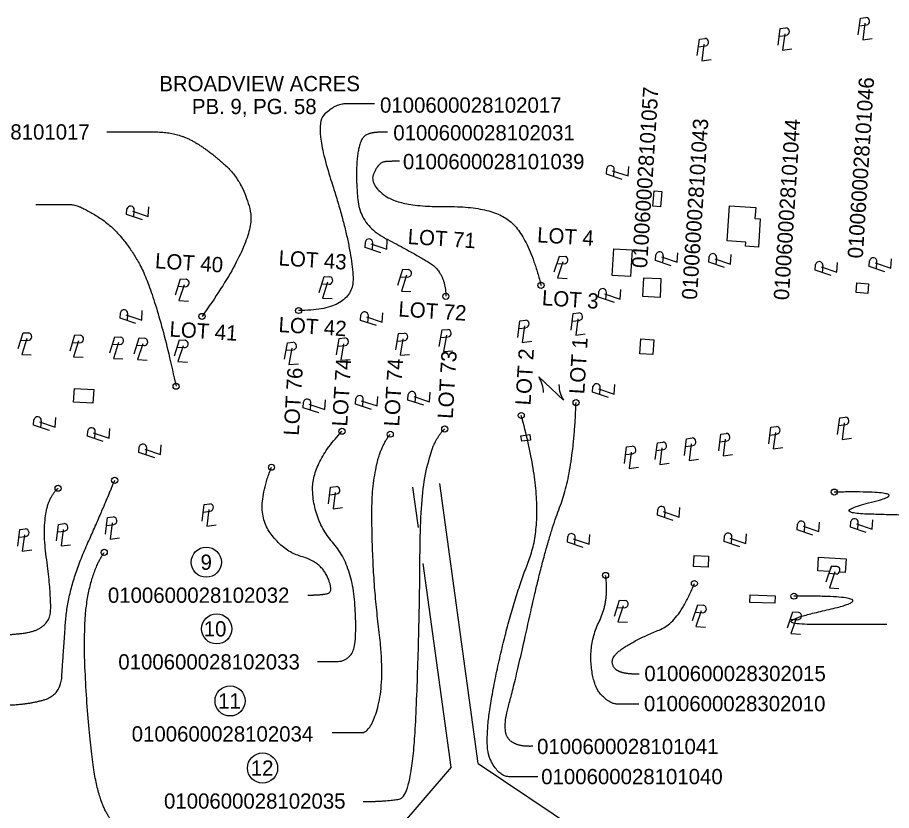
# Model space of a CAD drawing. Extents: x 1571291 to 1576333, y 700252 to 704384.
# Drawn here: x 1572970 to 1574575, y 702532 to 703989 of the extents above; entities that cross this region are included whole.
import ezdxf

# ---------------------------------------------------------------- set-up
doc = ezdxf.new("R2010")
doc.units = 0
doc.layers.add('RW_X_CL_100_Bearings', color=7, linetype='Continuous')
doc.layers.add('RW_X_CL_100_Cardinal_Points', color=7, linetype='Continuous')

msp = doc.modelspace()

# ---------------------------------------------------------------- linework, layer by layer
at = {"layer": 'RW_X_CL_100_Bearings'}
for p, q in [((1573706.1, 703051.9), (1573696, 703126.4)), ((1573815.6, 702618.7), (1573745.5, 703133.2)), ((1573766.1, 702611.9), (1573715.1, 702986.1)), ((1573766.1, 702611.9), (1573530.6, 702338.1)), ((1573815.6, 702618.7), (1574165.4, 702384.7))]:
    msp.add_line(p, q, dxfattribs=at)
for points in [[(1574136.6, 703642.4), (1574139.1, 703670.4), (1574153.3, 703669.2), (1574150.8, 703641.1)], [(1574273, 703578.4), (1574277, 703642.9), (1574325.3, 703640), (1574324, 703619.7), (1574333.5, 703619.1), (1574330.3, 703567.1), (1574306.6, 703568.5), (1574307.1, 703576.3)], [(1574061.8, 703515.2), (1574064.7, 703563.8), (1574098.4, 703561.8), (1574095.4, 703513.2)], [(1574118.4, 703476.4), (1574120.2, 703510.8), (1574151.5, 703509.2), (1574149.7, 703474.7)], [(1574509.7, 703483.4), (1574511, 703501.2), (1574532.3, 703499.6), (1574531.1, 703481.9)], [(1574114.4, 703398.5), (1574138.6, 703396.7), (1574136.6, 703369.6), (1574112.4, 703371.3)], [(1573073.3, 703282.5), (1573075, 703307.6), (1573110.5, 703305.3), (1573108.8, 703280.2)], [(1573896, 703210.4), (1573894.3, 703220.7), (1573910.5, 703222.9), (1573912, 703212.6)], [(1574237.8, 702979.2), (1574210.9, 702980.8), (1574212.1, 703000.9), (1574239, 702999.3)], [(1574314.6, 702914.6), (1574315.1, 702928.5), (1574361.1, 702926.9), (1574360.7, 702913.1)]]:
    msp.add_lwpolyline(points, close=True, dxfattribs=at)
msp.add_lwpolyline([(1574474.8, 702980.6), (1574464.5, 702981.4), (1574461.1, 702971.5), (1574439.5, 702972.7), (1574440.9, 702997.4), (1574491.2, 702994.5), (1574489.8, 702969.8), (1574479.2, 702970.4)], dxfattribs=at)
for centre, radius in [((1573931.3, 703496.8), 5.6), ((1573756.5, 703476.7), 5.6), ((1573309, 703439.7), 5.6), ((1573486.2, 703450.6), 5.6), ((1573261.4, 703311.6), 5.6), ((1573995.6, 703281.6), 5.6), ((1573895, 703257.8), 5.6), ((1573754.5, 703233.1), 5.6), ((1573565.9, 703228.9), 5.6), ((1573654.4, 703223.5), 5.6), ((1573436.5, 703162.8), 5.6), ((1573148.7, 703138.8), 5.6), ((1573044.7, 703124.2), 5.6), ((1574469.6, 703117.1), 5.6), ((1573129.5, 703006.5), 5.6), ((1573316.8, 702988.4), 27.7), ((1574049.8, 702964.1), 5.6), ((1574212.8, 702949.3), 5.6), ((1574395.6, 702926), 5.6), ((1573335.9, 702866), 27.7), ((1573360.5, 702733.7), 27.7), ((1573420.1, 702610.4), 27.7)]:
    msp.add_circle(centre, radius, dxfattribs=at)
msp.add_arc((1574473.2, 702973.9), 6.9, 329.6631, 77.0927, dxfattribs=at)
for points in [[(1573625.7, 703830), (1573587.7, 703830), (1573554, 703830), (1573512.8, 703790.9), (1573580.9, 703581.9), (1573591.4, 703450), (1573486.2, 703450.6)], [(1573134.2, 703778.5), (1573185.1, 703778.5), (1573262.4, 703778.5), (1573322.8, 703744.6), (1573386.1, 703684.9), (1573409.1, 703580.1), (1573309, 703439.7)], [(1573649.2, 703777.9), (1573618.5, 703779.3), (1573597.8, 703764.1), (1573590.4, 703699.6), (1573599.9, 703606.8), (1573693.8, 703558.2), (1573756.4, 703520.3), (1573756.5, 703476.7)], [(1573671.7, 703724.9), (1573654.9, 703724.7), (1573634.2, 703723.1), (1573615, 703683.6), (1573673.5, 703640.5), (1573842.1, 703642.4), (1573908.9, 703584.8), (1573931.3, 703496.8)], [(1573003.6, 703645.3), (1573051.8, 703645.3), (1573083.5, 703645.3), (1573161.2, 703594.5), (1573224.1, 703482.9), (1573261.4, 703311.6)], [(1573916.5, 702650.4), (1573882, 702648.8), (1573859.6, 702681.9), (1573884.1, 702768.8), (1573940.6, 703025.1), (1573991.2, 703154.9), (1573995.6, 703281.6)], [(1573925.7, 702594.5), (1573891.2, 702594.5), (1573853.9, 702594.5), (1573822.9, 702656.4), (1573873.5, 702900.6), (1573944.3, 703082.6), (1573895, 703257.8)], [(1573521, 702806.3), (1573545.2, 702806.3), (1573573.2, 702806.3), (1573594.6, 702835.5), (1573584.9, 702983.2), (1573516.2, 703061.6), (1573508.2, 703168.1), (1573565.9, 703228.9)], [(1573548, 702675.7), (1573583.1, 702675.7), (1573619.6, 702675), (1573645.1, 702775.1), (1573621.8, 702958.7), (1573619.7, 703180.2), (1573654.4, 703223.5)], [(1573604.8, 702548.9), (1573648.6, 702548.9), (1573695.1, 702558.6), (1573708.1, 702849.3), (1573710.7, 703193.5), (1573754.5, 703233.1)], [(1573503.1, 702928), (1573528.3, 702928), (1573551.4, 702934.2), (1573526.6, 702989.2), (1573455.3, 703008.9), (1573405.8, 703086.9), (1573436.5, 703162.8)], [(1572939, 702725.9), (1572983.1, 702725.9), (1573049.4, 702743.7), (1573053.8, 702812.4), (1573062.7, 702941.2), (1573128.7, 703089.5), (1573148.7, 703138.8)], [(1572919.6, 702854.8), (1572979.9, 702854.8), (1573023.3, 702870.6), (1573035.2, 702906.9), (1573010.7, 703093.5), (1573044.7, 703124.2)], [(1574633.4, 703074.3), (1574608.3, 703074.3), (1574457.1, 703078.9), (1574624.6, 703119.9), (1574469.6, 703117.1)], [(1573224.8, 702489.4), (1573170, 702487.3), (1573128.6, 702526.8), (1573105.3, 702620.5), (1573088.8, 702862.5), (1573107.7, 702975.4), (1573129.5, 703006.5)], [(1574110.6, 702727.8), (1574085.9, 702727.8), (1574058.5, 702727.8), (1574026.6, 702760.2), (1574019.9, 702842.4), (1574056.7, 702917.9), (1574049.8, 702964.1)], [(1574111.5, 702782.7), (1574084.5, 702782.7), (1574062.1, 702793.9), (1574062.1, 702818.6), (1574115.1, 702851), (1574184.7, 702878.4), (1574212.8, 702949.3)], [(1574566, 702874), (1574534.6, 702874), (1574336.2, 702874), (1574575.6, 702927.4), (1574395.6, 702926)]]:
    msp.add_open_spline(points, degree=2, dxfattribs=at)
at = {"layer": 'RW_X_CL_100_Cardinal_Points'}
for p, q in [((1574515.6, 703973.4), (1574528.5, 703975)), ((1574524.4, 703968.2), (1574524.4, 703968.2)), ((1574368.5, 703954.3), (1574381.3, 703955.9)), ((1574377.2, 703949.1), (1574377.2, 703949.1)), ((1574220.2, 703935), (1574233.1, 703936.7)), ((1574229, 703929.9), (1574229, 703929.9)), ((1574064.7, 703696.6), (1574065.6, 703709.5)), ((1574071.5, 703704.2), (1574071.5, 703704.2)), ((1573183.9, 703622.3), (1573184.7, 703635.2)), ((1573190.6, 703629.9), (1573190.6, 703629.9)), ((1573621.7, 703561.9), (1573622.4, 703574.8)), ((1573628.4, 703569.5), (1573628.4, 703569.5)), ((1574154.9, 703538.2), (1574155.8, 703551.1)), ((1574161.6, 703545.7), (1574161.6, 703545.7)), ((1574252.8, 703534.9), (1574253.7, 703547.8)), ((1574259.5, 703542.4), (1574259.5, 703542.4)), ((1574547, 703527.2), (1574547.9, 703540.1)), ((1573960.5, 703537.1), (1573973.5, 703536.3)), ((1573968.1, 703530.4), (1573968.1, 703530.4)), ((1574448, 703520.1), (1574448.9, 703533)), ((1574454.8, 703527.7), (1574454.8, 703527.7)), ((1574553.8, 703534.7), (1574553.8, 703534.7)), ((1573673.4, 703512.7), (1573686.3, 703512.1)), ((1573265.2, 703495.1), (1573278.2, 703494.4)), ((1573528.8, 703499.5), (1573541.7, 703498.9)), ((1573536.5, 703492.9), (1573536.5, 703492.9)), ((1573681.1, 703506.1), (1573681.1, 703506.1)), ((1573272.9, 703488.4), (1573272.9, 703488.4)), ((1574050.4, 703470.6), (1574051.2, 703483.5)), ((1574057.1, 703478.2), (1574057.1, 703478.2)), ((1573172, 703431.8), (1573172.8, 703444.8)), ((1573178.7, 703439.4), (1573178.7, 703439.4)), ((1573613.5, 703427.9), (1573614.3, 703440.9)), ((1573620.2, 703435.6), (1573620.2, 703435.6)), ((1573988.7, 703430.8), (1574001.6, 703432.5)), ((1573890.6, 703417.4), (1573903.4, 703419.1)), ((1573899.4, 703412.3), (1573899.4, 703412.3)), ((1573997.5, 703425.7), (1573997.5, 703425.7)), ((1572976.3, 703396.4), (1572989.2, 703395.8)), ((1573667.4, 703394.4), (1573680.4, 703395.5)), ((1573747.3, 703401), (1573760.2, 703402.1)), ((1573755.8, 703395.5), (1573755.8, 703395.5)), ((1572984, 703389.8), (1572984, 703389.8)), ((1573071.6, 703392.1), (1573084.6, 703391.5)), ((1573079.3, 703385.5), (1573079.3, 703385.5)), ((1573144.8, 703388.8), (1573157.7, 703388.3)), ((1573152.5, 703382.3), (1573152.5, 703382.3)), ((1573189.3, 703386.8), (1573202.2, 703386.1)), ((1573197, 703380.1), (1573197, 703380.1)), ((1573263.4, 703383), (1573276.3, 703382.4)), ((1573558.6, 703385.4), (1573571.5, 703386.4)), ((1573567.1, 703379.8), (1573567.1, 703379.8)), ((1573675.9, 703388.9), (1573675.9, 703388.9)), ((1573271.1, 703376.4), (1573271.1, 703376.4)), ((1573463.4, 703377.5), (1573476.4, 703378.5)), ((1573471.9, 703371.9), (1573471.9, 703371.9)), ((1573972.7, 703285.8), (1573927.3, 703328.6)), ((1573950, 703307.2), (1573950, 703307.2)), ((1574039.2, 703296), (1574040.1, 703308.9)), ((1574046, 703303.6), (1574046, 703303.6)), ((1573604.2, 703274.2), (1573604.9, 703287.1)), ((1573700.4, 703281.8), (1573701.2, 703294.7)), ((1573707.1, 703289.4), (1573707.1, 703289.4)), ((1573508, 703267.7), (1573508.8, 703280.6)), ((1573514.7, 703275.3), (1573514.7, 703275.3)), ((1573610.9, 703281.8), (1573610.9, 703281.8)), ((1573013.2, 703235.4), (1573014, 703248.3)), ((1573019.9, 703243), (1573019.9, 703243)), ((1574477.9, 703239.3), (1574490.7, 703241)), ((1573112.1, 703215.1), (1573112.9, 703228.1)), ((1573118.8, 703222.7), (1573118.8, 703222.7)), ((1574351.4, 703222), (1574364.2, 703223.8)), ((1574486.6, 703234.2), (1574486.6, 703234.2)), ((1574259.4, 703209.5), (1574272.2, 703211.3)), ((1574268.2, 703204.4), (1574268.2, 703204.4)), ((1574360.1, 703216.9), (1574360.1, 703216.9)), ((1573206.6, 703185.3), (1573207.4, 703198.2)), ((1573213.3, 703192.9), (1573213.3, 703192.9)), ((1574086.6, 703186), (1574099.4, 703187.7)), ((1574143.1, 703193.7), (1574156, 703195.4)), ((1574151.9, 703188.6), (1574151.9, 703188.6)), ((1574196.8, 703201), (1574209.7, 703202.7)), ((1574205.6, 703195.9), (1574205.6, 703195.9)), ((1574095.4, 703180.9), (1574095.4, 703180.9)), ((1573543.3, 703111.9), (1573556.1, 703113.7)), ((1573552.1, 703106.8), (1573552.1, 703106.8)), ((1573311.3, 703080.3), (1573324.1, 703082)), ((1573320, 703075.2), (1573320, 703075.2)), ((1574158.3, 703070.5), (1574159.2, 703083.4)), ((1574165, 703078), (1574165, 703078)), ((1574512.6, 703048.1), (1574513.6, 703061)), ((1573044, 703043.9), (1573056.8, 703045.6)), ((1573134, 703056.1), (1573146.9, 703057.9)), ((1573142.8, 703051), (1573142.8, 703051)), ((1574414.8, 703043.5), (1574415.7, 703056.4)), ((1574421.6, 703051.1), (1574421.6, 703051.1)), ((1574519.4, 703055.6), (1574519.4, 703055.6)), ((1572972.7, 703034.1), (1572985.5, 703035.9)), ((1572981.5, 703029), (1572981.5, 703029)), ((1573052.7, 703038.8), (1573052.7, 703038.8)), ((1573993.1, 703020.7), (1573993.9, 703033.6)), ((1573999.8, 703028.3), (1573999.8, 703028.3)), ((1574280.8, 703021.8), (1574281.7, 703034.7)), ((1574287.5, 703029.3), (1574287.5, 703029.3)), ((1574459.9, 702968), (1574472.8, 702967)), ((1574467.4, 702961.1), (1574467.4, 702961.1)), ((1574071.1, 702905.3), (1574084, 702904.6)), ((1574078.8, 702898.7), (1574078.8, 702898.7)), ((1574214.6, 702896.6), (1574227.6, 702895.7)), ((1574222.2, 702889.8), (1574222.2, 702889.8)), ((1574389.2, 702883.7), (1574402.1, 702882.7)), ((1574396.7, 702876.9), (1574396.7, 702876.9))]:
    msp.add_line(p, q, dxfattribs=at)
for points in [[(1574513.5, 703957), (1574517.5, 703987.4), (1574527.7, 703988.8)], [(1574525.8, 703978.1), (1574521.8, 703947.7), (1574539.1, 703950)], [(1574366.3, 703937.9), (1574370.3, 703968.3), (1574380.5, 703969.7)], [(1574378.6, 703959), (1574374.6, 703928.6), (1574391.9, 703930.9)], [(1574218.1, 703918.7), (1574222, 703949.1), (1574232.3, 703950.4)], [(1574230.4, 703939.7), (1574226.3, 703909.4), (1574243.7, 703911.6)], [(1574080.4, 703691.4), (1574051.3, 703701), (1574051.9, 703711.4)], [(1574062.1, 703707.4), (1574091.1, 703697.7), (1574092.2, 703715.1)], [(1573199.5, 703617.1), (1573170.4, 703626.8), (1573171, 703637.1)], [(1573181.2, 703633.2), (1573210.2, 703623.4), (1573211.3, 703640.9)], [(1573637.3, 703556.7), (1573608.2, 703566.3), (1573608.8, 703576.6)], [(1573618.9, 703572.8), (1573648, 703563.1), (1573649, 703580.5)], [(1574152.2, 703549.1), (1574181.2, 703539.1), (1574182.4, 703556.5)], [(1573955.3, 703521.5), (1573965, 703550.6), (1573975.3, 703549.9)], [(1573971.4, 703539.8), (1573961.6, 703510.8), (1573979, 703509.7)], [(1574170.4, 703532.9), (1574141.4, 703542.7), (1574142.1, 703553)], [(1574268.3, 703529.6), (1574239.3, 703539.4), (1574240.1, 703549.7)], [(1574250.2, 703545.8), (1574279.1, 703535.8), (1574280.3, 703553.2)], [(1574562.6, 703521.9), (1574533.6, 703531.7), (1574534.3, 703542)], [(1574544.4, 703538.1), (1574573.3, 703528.1), (1574574.6, 703545.5)], [(1573668.4, 703497), (1573677.6, 703526.3), (1573687.9, 703525.8)], [(1574463.6, 703514.8), (1574434.6, 703524.7), (1574435.3, 703535)], [(1574445.4, 703531), (1574474.3, 703521), (1574475.6, 703538.5)], [(1573260.2, 703479.4), (1573269.5, 703508.6), (1573279.8, 703508.1)], [(1573523.8, 703483.8), (1573533, 703513), (1573543.3, 703512.5)], [(1573684.2, 703515.6), (1573674.9, 703486.4), (1573692.4, 703485.6)], [(1573276, 703497.9), (1573266.6, 703468.8), (1573284.1, 703467.9)], [(1573539.6, 703502.4), (1573530.3, 703473.2), (1573547.7, 703472.4)], [(1574066, 703465.4), (1574036.9, 703475.1), (1574037.5, 703485.4)], [(1574047.7, 703481.5), (1574076.7, 703471.7), (1574077.8, 703489.1)], [(1573187.6, 703426.6), (1573158.5, 703436.3), (1573159.1, 703446.6)], [(1573169.3, 703442.7), (1573198.3, 703433), (1573199.4, 703450.4)], [(1573610.8, 703438.8), (1573639.8, 703429.1), (1573640.9, 703446.5)], [(1573986.7, 703414.4), (1573990.4, 703444.9), (1574000.7, 703446.2)], [(1573629.1, 703422.8), (1573600, 703432.4), (1573600.7, 703442.7)], [(1573888.6, 703401), (1573892.3, 703431.5), (1573902.5, 703432.9)], [(1573998.8, 703435.5), (1573995, 703405.2), (1574012.3, 703407.5)], [(1573744.4, 703384.8), (1573749.8, 703415), (1573760.1, 703415.9)], [(1573900.7, 703422.2), (1573896.9, 703391.8), (1573914.2, 703394.2)], [(1572971.4, 703380.7), (1572980.5, 703409.9), (1572990.8, 703409.5)], [(1572987.1, 703399.3), (1572977.9, 703370.1), (1572995.3, 703369.3)], [(1573066.7, 703376.4), (1573075.8, 703405.7), (1573086.2, 703405.2)], [(1573139.8, 703373.1), (1573149, 703402.4), (1573159.3, 703401.9)], [(1573184.3, 703371.1), (1573193.6, 703400.3), (1573203.9, 703399.8)], [(1573258.4, 703367.3), (1573267.7, 703396.6), (1573278, 703396)], [(1573555.7, 703369.2), (1573561, 703399.4), (1573571.3, 703400.2)], [(1573664.6, 703378.2), (1573669.9, 703408.4), (1573680.2, 703409.2)], [(1573677.8, 703398.7), (1573672.4, 703368.5), (1573689.8, 703370)], [(1573757.7, 703405.3), (1573752.2, 703375.2), (1573769.6, 703376.6)], [(1573082.4, 703395), (1573073.2, 703365.8), (1573090.7, 703365)], [(1573155.6, 703391.7), (1573146.3, 703362.5), (1573163.8, 703361.8)], [(1573200.1, 703389.6), (1573190.7, 703360.5), (1573208.2, 703359.6)], [(1573274.2, 703385.9), (1573264.8, 703356.7), (1573282.3, 703355.8)], [(1573460.6, 703361.3), (1573465.9, 703391.5), (1573476.2, 703392.3)], [(1573473.8, 703381.7), (1573468.4, 703351.6), (1573485.8, 703353)], [(1573568.9, 703389.6), (1573563.5, 703359.5), (1573580.9, 703360.9)], [(1573697.7, 703292.7), (1573726.7, 703283), (1573727.8, 703300.4)], [(1574054.9, 703290.8), (1574025.8, 703300.5), (1574026.4, 703310.8)], [(1574036.6, 703306.9), (1574065.6, 703297.1), (1574066.7, 703314.5)], [(1573505.3, 703278.6), (1573534.3, 703268.9), (1573535.4, 703286.3)], [(1573619.8, 703269), (1573590.7, 703278.6), (1573591.3, 703288.9)], [(1573601.4, 703285), (1573630.5, 703275.3), (1573631.5, 703292.8)], [(1573716, 703276.6), (1573686.9, 703286.2), (1573687.5, 703296.5)], [(1573523.6, 703262.5), (1573494.5, 703272.1), (1573495.2, 703282.5)], [(1573010.5, 703246.3), (1573039.5, 703236.5), (1573040.6, 703254)], [(1574475.8, 703222.9), (1574479.6, 703253.4), (1574489.8, 703254.8)], [(1573028.8, 703230.2), (1572999.7, 703239.8), (1573000.3, 703250.2)], [(1574349.3, 703205.7), (1574353.1, 703236.1), (1574363.3, 703237.5)], [(1574488, 703244.1), (1574484.1, 703213.7), (1574501.4, 703216.1)], [(1573127.8, 703209.9), (1573098.6, 703219.6), (1573099.3, 703229.9)], [(1573109.4, 703226), (1573138.4, 703216.3), (1573139.5, 703233.7)], [(1574257.4, 703193.2), (1574261.1, 703223.6), (1574271.3, 703225)], [(1574361.5, 703226.8), (1574357.6, 703196.5), (1574374.9, 703198.8)], [(1573203.9, 703196.2), (1573232.9, 703186.5), (1573234, 703203.9)], [(1574141.1, 703177.3), (1574144.9, 703207.8), (1574155.1, 703209.1)], [(1574194.8, 703184.6), (1574198.6, 703215.1), (1574208.8, 703216.5)], [(1574207, 703205.8), (1574203.1, 703175.4), (1574220.4, 703177.8)], [(1574269.5, 703214.3), (1574265.7, 703183.9), (1574283, 703186.3)], [(1573222.2, 703180.1), (1573193.1, 703189.8), (1573193.8, 703200.1)], [(1574084.6, 703169.6), (1574088.3, 703200.1), (1574098.6, 703201.4)], [(1574096.7, 703190.7), (1574092.9, 703160.4), (1574110.2, 703162.7)], [(1574153.3, 703198.4), (1574149.4, 703168.1), (1574166.7, 703170.4)], [(1573541.3, 703095.6), (1573545, 703126), (1573555.3, 703127.4)], [(1573553.4, 703116.7), (1573549.6, 703086.3), (1573566.9, 703088.7)], [(1573309.3, 703063.9), (1573313, 703094.4), (1573323.2, 703095.8)], [(1573321.4, 703085.1), (1573317.5, 703054.7), (1573334.9, 703057.1)], [(1574173.9, 703065.2), (1574144.8, 703075), (1574145.5, 703085.3)], [(1574155.6, 703081.3), (1574184.6, 703071.4), (1574185.8, 703088.9)], [(1573041.9, 703027.5), (1573045.7, 703057.9), (1573055.9, 703059.3)], [(1573132, 703039.8), (1573135.7, 703070.2), (1573146, 703071.6)], [(1573144.1, 703060.9), (1573140.3, 703030.5), (1573157.6, 703032.9)], [(1574412.2, 703054.4), (1574441.2, 703044.5), (1574442.4, 703061.9)], [(1574528.2, 703042.7), (1574499.2, 703052.7), (1574500, 703063)], [(1574510.1, 703059), (1574539, 703048.9), (1574540.3, 703066.3)], [(1572970.7, 703017.8), (1572974.4, 703048.2), (1572984.6, 703049.6)], [(1573054.1, 703048.6), (1573050.2, 703018.3), (1573067.5, 703020.6)], [(1574430.4, 703038.2), (1574401.4, 703048.1), (1574402.1, 703058.4)], [(1572982.8, 703038.9), (1572978.9, 703008.5), (1572996.3, 703010.9)], [(1574008.6, 703015.4), (1573979.6, 703025.2), (1573980.3, 703035.6)], [(1573990.4, 703031.6), (1574019.4, 703021.7), (1574020.6, 703039.1)], [(1574296.4, 703016.5), (1574267.3, 703026.3), (1574268, 703036.6)], [(1574278.1, 703032.7), (1574307.1, 703022.7), (1574308.3, 703040.2)], [(1574454.5, 702952.4), (1574464.5, 702981.4), (1574474.8, 702980.6)], [(1574470.8, 702970.5), (1574460.7, 702941.6), (1574478.1, 702940.3)], [(1574066.1, 702889.6), (1574075.4, 702918.8), (1574085.7, 702918.3)], [(1574081.9, 702908.1), (1574072.5, 702879), (1574090, 702878.1)], [(1574209.3, 702881.1), (1574219.2, 702910.1), (1574229.5, 702909.3)], [(1574225.5, 702899.2), (1574215.4, 702870.3), (1574232.9, 702869)], [(1574383.8, 702868.1), (1574393.8, 702897.1), (1574404.1, 702896.4)], [(1574400.1, 702886.3), (1574390, 702857.4), (1574407.4, 702856.1)]]:
    msp.add_lwpolyline(points, dxfattribs=at)
for centre, radius, start, end in [((1574527.6, 703981.9), 6.9, 277.8688, 88.7259), ((1574380.4, 703962.8), 6.9, 277.8688, 88.7259), ((1574232.1, 703943.5), 6.9, 277.8688, 88.7259), ((1574058.7, 703709.9), 6.9, 356.8295, 167.6866), ((1573177.8, 703635.6), 6.9, 356.9017, 167.7588), ((1573615.6, 703575.2), 6.9, 356.9906, 167.8477), ((1574148.9, 703551.5), 6.9, 356.466, 167.3231), ((1573973.9, 703543.2), 6.9, 266.7929, 77.65), ((1574246.8, 703548.2), 6.9, 356.466, 167.3231), ((1574442, 703533.5), 6.9, 356.466, 167.3231), ((1574541, 703540.5), 6.9, 356.466, 167.3231), ((1573686.6, 703519), 6.9, 267.8147, 78.6718), ((1573278.4, 703501.3), 6.9, 267.5823, 78.4394), ((1573542, 703505.8), 6.9, 267.7914, 78.6485), ((1574044.3, 703483.9), 6.9, 356.8295, 167.6866), ((1573165.9, 703445.1), 6.9, 356.9017, 167.7588), ((1573607.4, 703441.2), 6.9, 356.9906, 167.8477), ((1574000.6, 703439.3), 6.9, 278.2323, 89.0894), ((1573902.4, 703426), 6.9, 278.2323, 89.0894), ((1573759.6, 703409), 6.9, 275.2183, 86.0754), ((1572989.5, 703402.7), 6.9, 267.9059, 78.763), ((1573084.8, 703398.4), 6.9, 267.9059, 78.763), ((1573158, 703395.2), 6.9, 267.9059, 78.763), ((1573202.5, 703393), 6.9, 267.5823, 78.4394), ((1573276.6, 703389.3), 6.9, 267.5823, 78.4394), ((1573570.9, 703393.3), 6.9, 275.2183, 86.0754), ((1573679.7, 703402.4), 6.9, 275.2183, 86.0754), ((1573475.7, 703385.4), 6.9, 275.2183, 86.0754), ((1573882.4, 703299.6), 53.4, 0.2141, 32.8566), ((1574033.2, 703309.3), 6.9, 356.8295, 167.6866), ((1573694.3, 703295.1), 6.9, 356.9906, 167.8477), ((1574017.6, 703314.7), 53.4, 180.2141, 212.8566), ((1573501.9, 703281), 6.9, 356.9906, 167.8477), ((1573598.1, 703287.5), 6.9, 356.9906, 167.8477), ((1573007.1, 703248.7), 6.9, 356.9604, 167.8175), ((1574489.7, 703247.9), 6.9, 278.2323, 89.0894), ((1573106, 703228.4), 6.9, 356.9604, 167.8175), ((1574363.2, 703230.6), 6.9, 278.2323, 89.0894), ((1574271.2, 703218.1), 6.9, 278.2323, 89.0894), ((1573200.5, 703198.6), 6.9, 356.9604, 167.8175), ((1574155, 703202.2), 6.9, 278.2323, 89.0894), ((1574208.7, 703209.6), 6.9, 278.2323, 89.0894), ((1574098.5, 703194.5), 6.9, 278.2323, 89.0894), ((1573555.1, 703120.5), 6.9, 278.2323, 89.0894), ((1573323.1, 703088.9), 6.9, 278.2323, 89.0894), ((1574152.3, 703083.8), 6.9, 356.5577, 167.4148), ((1573055.8, 703052.4), 6.9, 278.2323, 89.0894), ((1573145.9, 703064.7), 6.9, 278.2323, 89.0894), ((1574408.8, 703056.9), 6.9, 356.5577, 167.4148), ((1574506.7, 703061.5), 6.9, 356.2728, 167.1299), ((1572984.5, 703042.7), 6.9, 278.2323, 89.0894), ((1573987.1, 703034.1), 6.9, 356.5577, 167.4148), ((1574274.8, 703035.1), 6.9, 356.5577, 167.4148), ((1574473.2, 702973.9), 6.9, 266.2356, 77.0927), ((1574084.3, 702911.5), 6.9, 267.6077, 78.4648), ((1574228, 702902.6), 6.9, 266.2356, 77.0927), ((1574402.6, 702889.6), 6.9, 266.2356, 77.0927)]:
    msp.add_arc(centre, radius, start, end, dxfattribs=at)

# ---------------------------------------------------------------- texts
at = {"layer": 'RW_X_CL_100_Bearings'}
for s, p in [('BROADVIEW ACRES', (1573230.6, 703853.3)), ('PB. 9, PG. 58', (1573290.4, 703811.3)), ('0100600028102017', (1573635.7, 703813.9)), ('0100600028101017', (1572769.7, 703764.6)), ('0100600028102031', (1573660.1, 703763.1)), ('0100600028101039', (1573677.8, 703710.1)), ('9', (1573306.3, 702974.4)), ('0100600028102032', (1573136.2, 702913.8)), ('10', (1573312.1, 702852)), ('0100600028102033', (1573155.3, 702791.4)), ('0100600028302015', (1574120.9, 702770)), ('11', (1573338.6, 702719.7)), ('0100600028302010', (1574120.2, 702714.7)), ('0100600028102034', (1573179.9, 702659.1)), ('0100600028101041', (1573924, 702636)), ('12', (1573398.5, 702596.4)), ('0100600028101040', (1573931.6, 702580.7)), ('0100600028102035', (1573239.2, 702535.8))]:
    msp.add_text(s, height=28, dxfattribs=at).set_placement(p)
for s, rotation, p in [('0100600028101046', 86.3585, (1574521.8, 703545.6)), ('0100600028101057', 86.3585, (1574125.8, 703527.9)), ('0100600028101043', 86.3585, (1574217.4, 703469.8)), ('0100600028101044', 86.3585, (1574386.1, 703469)), ('LOT 71', 356.322, (1573685.9, 703572.8)), ('LOT 4', 356.322, (1573923.5, 703576)), ('LOT 40', 356.322, (1573222.1, 703528.3)), ('LOT 43', 356.322, (1573448.9, 703533.6)), ('LOT 3', 356.322, (1573932.3, 703460.4)), ('LOT 72', 356.322, (1573668.8, 703439.8)), ('LOT 41', 356.322, (1573248.6, 703402.9)), ('LOT 42', 356.322, (1573448.8, 703411.2)), ('LOT 1', 86.5196, (1574010.7, 703296.5)), ('LOT 73', 86.5196, (1573769.1, 703251.2)), ('LOT 2', 86.5196, (1573912, 703275.9)), ('LOT 74', 86.5196, (1573575.4, 703237.1)), ('LOT 74', 86.5196, (1573670.7, 703237.1)), ('LOT 76', 86.5196, (1573486.4, 703220.3))]:
    msp.add_text(s, height=28, rotation=rotation, dxfattribs=at).set_placement(p)

doc.saveas('drawing.dxf')
